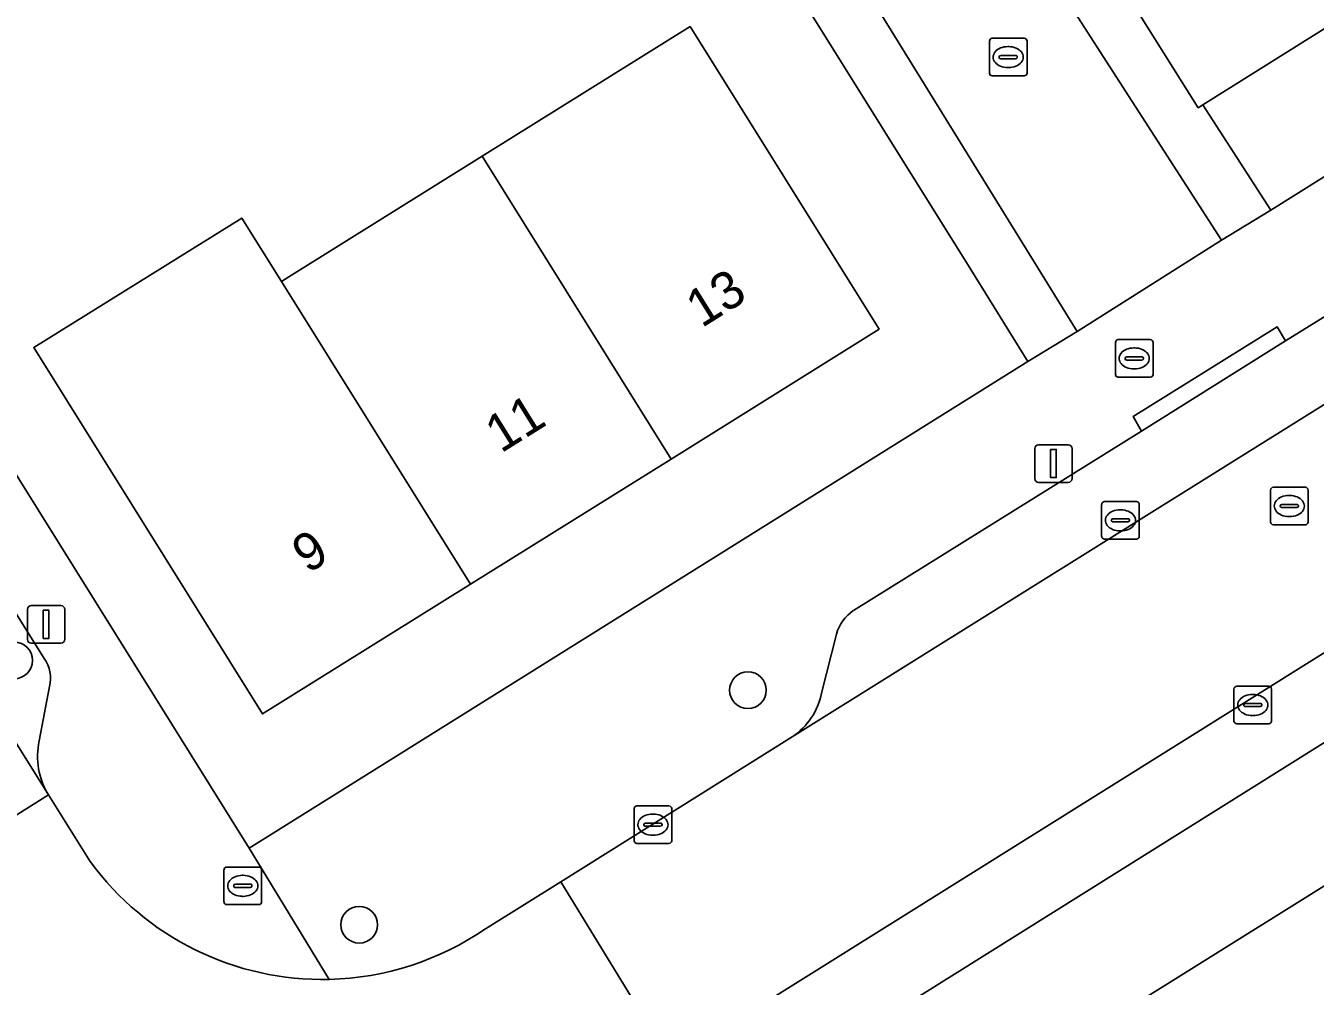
# Model space of a CAD drawing. Extents: x 159664 to 160323, y 385312 to 386115.
# Drawn here: x 160042.74 to 160077.07, y 385840.21 to 385865.77 of the extents above; entities that cross this region are included whole.
import ezdxf

# ---------------------------------------------------------------- set-up
doc = ezdxf.new("R2010")
doc.units = 0
for name, color, linetype in [('IMGEO_Boom', 7, 'Continuous'), ('IMGEO_Brandkraan', 7, 'Continuous'), ('IMGEO_Erf', 7, 'Continuous'), ('IMGEO_Kolk', 7, 'Continuous'), ('IMGEO_Lichtmast', 7, 'Continuous'), ('IMGEO_Muur', 7, 'Continuous'), ('IMGEO_Pand', 7, 'Continuous'), ('IMGEO_Pand_nummerreeks', 7, 'Continuous'), ('IMGEO_Parkeervlak_open', 7, 'Continuous'), ('IMGEO_Rijbaan_lokaal_open', 7, 'Continuous'), ('IMGEO_Rioolput', 7, 'Continuous'), ('IMGEO_Voetpad_open', 7, 'Continuous')]:
    doc.layers.add(name, color=color, linetype=linetype)

msp = doc.modelspace()

# ---------------------------------------------------------------- linework, layer by layer
at = {"layer": 'IMGEO_Boom'}
for centre in [(160042.431, 385848.879), (160061.965, 385848.085), (160051.616, 385841.843)]:
    msp.add_circle(centre, 0.489, dxfattribs=at)
at = {"layer": 'IMGEO_Brandkraan'}
for p, q in [((160071.749, 385856.491), (160071.749, 385857.343)), ((160071.824, 385857.417), (160072.676, 385857.417)), ((160072.75, 385857.343), (160072.75, 385856.491)), ((160072.008, 385856.911), (160072.008, 385856.923)), ((160072.051, 385856.96), (160072.449, 385856.96)), ((160072.237, 385857.197), (160072.262, 385857.197)), ((160072.492, 385856.923), (160072.492, 385856.911)), ((160072.446, 385856.874), (160072.048, 385856.874)), ((160072.26, 385856.637), (160072.235, 385856.637)), ((160072.676, 385856.417), (160071.824, 385856.417)), ((160048.016, 385842.452), (160048.016, 385843.304)), ((160048.091, 385843.378), (160048.943, 385843.378)), ((160049.017, 385843.304), (160049.017, 385842.452)), ((160048.275, 385842.872), (160048.275, 385842.884)), ((160048.318, 385842.921), (160048.716, 385842.921)), ((160048.504, 385843.158), (160048.529, 385843.158)), ((160048.759, 385842.884), (160048.759, 385842.872)), ((160048.713, 385842.835), (160048.315, 385842.835)), ((160048.527, 385842.598), (160048.502, 385842.598)), ((160048.943, 385842.378), (160048.091, 385842.378))]:
    msp.add_line(p, q, dxfattribs=at)
for points in [[(160071.749, 385856.491), (160071.749, 385857.343)], [(160071.824, 385857.417), (160072.676, 385857.417)], [(160072.75, 385857.343), (160072.75, 385856.491)], [(160072.676, 385856.417), (160071.824, 385856.417)], [(160048.016, 385842.452), (160048.016, 385843.304)], [(160048.091, 385843.378), (160048.943, 385843.378)], [(160049.017, 385843.304), (160049.017, 385842.452)], [(160048.943, 385842.378), (160048.091, 385842.378)]]:
    msp.add_lwpolyline(points, dxfattribs=at)
for centre, radius, start, end in [((160071.826, 385857.341), 0.0765, 91.552, 178.448), ((160071.826, 385857.341), 0.0765, 91.552, 178.448), ((160072.674, 385857.341), 0.0765, 1.552, 88.448), ((160072.674, 385857.341), 0.0765, 1.552, 88.448), ((160072.048, 385856.92), 0.0403, 85.8775, 175.7526), ((160072.453, 385856.922), 0.0386, 1.7309, 96.639), ((160072.045, 385856.91), 0.0366, 178.938, 274.7102), ((160072.449, 385856.917), 0.043, 264.8664, 352.4533), ((160071.826, 385856.493), 0.0765, 181.552, 268.448), ((160071.826, 385856.493), 0.0765, 181.552, 268.448), ((160072.674, 385856.493), 0.0765, 271.552, 358.448), ((160072.674, 385856.493), 0.0765, 271.552, 358.448), ((160048.093, 385843.302), 0.0765, 91.552, 178.448), ((160048.093, 385843.302), 0.0765, 91.552, 178.448), ((160048.941, 385843.302), 0.0765, 1.552, 88.448), ((160048.941, 385843.302), 0.0765, 1.552, 88.448), ((160048.315, 385842.881), 0.0403, 85.8775, 175.7526), ((160048.312, 385842.871), 0.0366, 178.938, 274.7102), ((160048.716, 385842.878), 0.043, 264.8664, 352.4533), ((160048.72, 385842.883), 0.0386, 1.7309, 96.639), ((160048.093, 385842.454), 0.0765, 181.552, 268.448), ((160048.093, 385842.454), 0.0765, 181.552, 268.448), ((160048.941, 385842.454), 0.0765, 271.552, 358.448), ((160048.941, 385842.454), 0.0765, 271.552, 358.448)]:
    msp.add_arc(centre, radius, start, end, dxfattribs=at)
for centre, major_axis, ratio, start_param, end_param in [((160072.236, 385856.917), (-0.387, 0.002), 0.722429, 4.712389, 7.853982), ((160072.261, 385856.917), (-0.39, 0.002), 0.717154, 1.570796, 4.712389), ((160048.503, 385842.878), (-0.387, 0.002), 0.722429, 4.712389, 7.853982), ((160048.528, 385842.878), (-0.39, 0.002), 0.717154, 1.570796, 4.712389)]:
    msp.add_ellipse(centre, major_axis=major_axis, ratio=ratio, start_param=start_param, end_param=end_param, dxfattribs=at)
at = {"layer": 'IMGEO_Erf'}
for points in [[(160017.562, 385899.151), (160016.976, 385898.786), (160016.864, 385898.967), (160013.411, 385904.508), (160011.524, 385903.327), (160035.946, 385864.298), (160048.683, 385843.877), (160069.417, 385856.837), (160067.895, 385859.287), (160061.072, 385870.217), (160056.435, 385867.318), (160052.008, 385874.381), (160051.226, 385875.622), (160036.993, 385866.722), (160033.548, 385872.248), (160030.317, 385877.411), (160029.732, 385877.045), (160029.621, 385877.223), (160026.283, 385882.566), (160026.158, 385882.766), (160027.345, 385883.508), (160024.13, 385888.65), (160020.789, 385893.991)], [(160116.716, 385886.45), (160114.912, 385889.321), (160109.699, 385886.046), (160104.61, 385882.849), (160099.521, 385879.652), (160094.432, 385876.454), (160089.342, 385873.256), (160084.253, 385870.059), (160079.165, 385866.862), (160074.076, 385863.665), (160075.884, 385860.864)], [(160042.951, 385857.21), (160048.489, 385860.652), (160049.543, 385858.965), (160049.744, 385859.091), (160054.888, 385862.299), (160060.425, 385865.751), (160065.456, 385857.696), (160059.924, 385854.239), (160054.578, 385850.905), (160049.045, 385847.455)]]:
    msp.add_lwpolyline(points, close=True, dxfattribs=at)
msp.add_lwpolyline([(160099.993, 385857.035), (160056.287, 385829.749), (160069.138, 385809.263), (160069.666, 385808.627)], dxfattribs=at)
at = {"layer": 'IMGEO_Kolk'}
for p, q in [((160068.394, 385864.512), (160068.394, 385865.364)), ((160068.469, 385865.438), (160069.321, 385865.438)), ((160068.882, 385865.218), (160068.907, 385865.218)), ((160069.395, 385865.364), (160069.395, 385864.512)), ((160068.653, 385864.932), (160068.653, 385864.944)), ((160069.091, 385864.895), (160068.693, 385864.895)), ((160068.696, 385864.981), (160069.094, 385864.981)), ((160069.137, 385864.944), (160069.137, 385864.932)), ((160068.905, 385864.658), (160068.88, 385864.658)), ((160069.321, 385864.438), (160068.469, 385864.438)), ((160071.382, 385852.181), (160071.382, 385853.033)), ((160071.457, 385853.107), (160072.309, 385853.107)), ((160071.87, 385852.887), (160071.895, 385852.887)), ((160072.383, 385853.033), (160072.383, 385852.181)), ((160071.641, 385852.601), (160071.641, 385852.613)), ((160072.079, 385852.564), (160071.681, 385852.564)), ((160071.684, 385852.65), (160072.082, 385852.65)), ((160072.125, 385852.613), (160072.125, 385852.601)), ((160071.893, 385852.327), (160071.868, 385852.327)), ((160072.309, 385852.107), (160071.457, 385852.107)), ((160074.904, 385847.265), (160074.904, 385848.117)), ((160074.979, 385848.191), (160075.831, 385848.191)), ((160075.905, 385848.117), (160075.905, 385847.265)), ((160075.163, 385847.685), (160075.163, 385847.697)), ((160075.206, 385847.734), (160075.604, 385847.734)), ((160075.392, 385847.971), (160075.417, 385847.971)), ((160075.647, 385847.697), (160075.647, 385847.685)), ((160075.601, 385847.648), (160075.203, 385847.648)), ((160075.415, 385847.411), (160075.39, 385847.411)), ((160075.831, 385847.191), (160074.979, 385847.191)), ((160058.935, 385844.08), (160058.935, 385844.932)), ((160059.01, 385845.006), (160059.862, 385845.006)), ((160059.936, 385844.932), (160059.936, 385844.08)), ((160059.423, 385844.786), (160059.448, 385844.786)), ((160059.194, 385844.5), (160059.194, 385844.512)), ((160059.632, 385844.463), (160059.234, 385844.463)), ((160059.237, 385844.549), (160059.635, 385844.549)), ((160059.446, 385844.226), (160059.421, 385844.226)), ((160059.678, 385844.512), (160059.678, 385844.5)), ((160059.862, 385844.006), (160059.01, 385844.006))]:
    msp.add_line(p, q, dxfattribs=at)
for points in [[(160068.394, 385864.512), (160068.394, 385865.364)], [(160068.469, 385865.438), (160069.321, 385865.438)], [(160069.395, 385865.364), (160069.395, 385864.512)], [(160069.321, 385864.438), (160068.469, 385864.438)], [(160071.382, 385852.181), (160071.382, 385853.033)], [(160071.457, 385853.107), (160072.309, 385853.107)], [(160072.383, 385853.033), (160072.383, 385852.181)], [(160072.309, 385852.107), (160071.457, 385852.107)], [(160074.904, 385847.265), (160074.904, 385848.117)], [(160074.979, 385848.191), (160075.831, 385848.191)], [(160075.905, 385848.117), (160075.905, 385847.265)], [(160075.831, 385847.191), (160074.979, 385847.191)], [(160058.935, 385844.08), (160058.935, 385844.932)], [(160059.01, 385845.006), (160059.862, 385845.006)], [(160059.936, 385844.932), (160059.936, 385844.08)], [(160059.862, 385844.006), (160059.01, 385844.006)]]:
    msp.add_lwpolyline(points, dxfattribs=at)
for centre, radius, start, end in [((160068.471, 385865.362), 0.0765, 91.552, 178.448), ((160068.471, 385865.362), 0.0765, 91.552, 178.448), ((160069.319, 385865.362), 0.0765, 1.552, 88.448), ((160069.319, 385865.362), 0.0765, 1.552, 88.448), ((160068.693, 385864.941), 0.0403, 85.8775, 175.7526), ((160068.69, 385864.931), 0.0366, 178.938, 274.7102), ((160069.094, 385864.938), 0.043, 264.8664, 352.4533), ((160069.098, 385864.943), 0.0386, 1.7309, 96.639), ((160068.471, 385864.514), 0.0765, 181.552, 268.448), ((160068.471, 385864.514), 0.0765, 181.552, 268.448), ((160069.319, 385864.514), 0.0765, 271.552, 358.448), ((160069.319, 385864.514), 0.0765, 271.552, 358.448), ((160071.459, 385853.031), 0.0765, 91.552, 178.448), ((160071.459, 385853.031), 0.0765, 91.552, 178.448), ((160072.307, 385853.031), 0.0765, 1.552, 88.448), ((160072.307, 385853.031), 0.0765, 1.552, 88.448), ((160071.681, 385852.61), 0.0403, 85.8775, 175.7526), ((160071.678, 385852.6), 0.0366, 178.938, 274.7102), ((160072.082, 385852.607), 0.043, 264.8664, 352.4533), ((160072.086, 385852.612), 0.0386, 1.7309, 96.639), ((160071.459, 385852.183), 0.0765, 181.552, 268.448), ((160071.459, 385852.183), 0.0765, 181.552, 268.448), ((160072.307, 385852.183), 0.0765, 271.552, 358.448), ((160072.307, 385852.183), 0.0765, 271.552, 358.448), ((160074.981, 385848.115), 0.0765, 91.552, 178.448), ((160074.981, 385848.115), 0.0765, 91.552, 178.448), ((160075.829, 385848.115), 0.0765, 1.552, 88.448), ((160075.829, 385848.115), 0.0765, 1.552, 88.448), ((160075.203, 385847.694), 0.0403, 85.8775, 175.7526), ((160075.2, 385847.684), 0.0366, 178.938, 274.7102), ((160075.604, 385847.691), 0.043, 264.8664, 352.4533), ((160075.608, 385847.696), 0.0386, 1.7309, 96.639), ((160074.981, 385847.267), 0.0765, 181.552, 268.448), ((160074.981, 385847.267), 0.0765, 181.552, 268.448), ((160075.829, 385847.267), 0.0765, 271.552, 358.448), ((160075.829, 385847.267), 0.0765, 271.552, 358.448), ((160059.012, 385844.93), 0.0765, 91.552, 178.448), ((160059.012, 385844.93), 0.0765, 91.552, 178.448), ((160059.86, 385844.93), 0.0765, 1.552, 88.448), ((160059.86, 385844.93), 0.0765, 1.552, 88.448), ((160059.234, 385844.509), 0.0403, 85.8775, 175.7526), ((160059.231, 385844.499), 0.0366, 178.938, 274.7102), ((160059.635, 385844.506), 0.043, 264.8664, 352.4533), ((160059.639, 385844.511), 0.0386, 1.7309, 96.639), ((160059.012, 385844.082), 0.0765, 181.552, 268.448), ((160059.012, 385844.082), 0.0765, 181.552, 268.448), ((160059.86, 385844.082), 0.0765, 271.552, 358.448), ((160059.86, 385844.082), 0.0765, 271.552, 358.448)]:
    msp.add_arc(centre, radius, start, end, dxfattribs=at)
for centre, major_axis, ratio, start_param, end_param in [((160068.881, 385864.938), (-0.387, 0.002), 0.722429, 4.712389, 7.853982), ((160068.906, 385864.938), (-0.39, 0.002), 0.717154, 1.570796, 4.712389), ((160071.869, 385852.607), (-0.387, 0.002), 0.722429, 4.712389, 7.853982), ((160071.894, 385852.607), (-0.39, 0.002), 0.717154, 1.570796, 4.712389), ((160075.391, 385847.691), (-0.387, 0.002), 0.722429, 4.712389, 7.853982), ((160075.416, 385847.691), (-0.39, 0.002), 0.717154, 1.570796, 4.712389), ((160059.422, 385844.506), (-0.387, 0.002), 0.722429, 4.712389, 7.853982), ((160059.447, 385844.506), (-0.39, 0.002), 0.717154, 1.570796, 4.712389)]:
    msp.add_ellipse(centre, major_axis=major_axis, ratio=ratio, start_param=start_param, end_param=end_param, dxfattribs=at)
at = {"layer": 'IMGEO_Lichtmast'}
for p, q in [((160069.604, 385853.718), (160069.604, 385854.518)), ((160069.604, 385854.518), (160069.604, 385853.718)), ((160069.704, 385854.618), (160070.494, 385854.618)), ((160070.494, 385854.618), (160069.704, 385854.618)), ((160070.594, 385854.518), (160070.594, 385853.718)), ((160070.594, 385853.718), (160070.594, 385854.518)), ((160070.494, 385853.618), (160069.704, 385853.618)), ((160069.704, 385853.618), (160070.494, 385853.618)), ((160042.786, 385849.437), (160042.786, 385850.237)), ((160042.786, 385850.237), (160042.786, 385849.437)), ((160042.886, 385850.337), (160043.676, 385850.337)), ((160043.676, 385850.337), (160042.886, 385850.337)), ((160043.776, 385850.237), (160043.776, 385849.437)), ((160043.776, 385849.437), (160043.776, 385850.237)), ((160043.676, 385849.337), (160042.886, 385849.337)), ((160042.886, 385849.337), (160043.676, 385849.337))]:
    msp.add_line(p, q, dxfattribs=at)
for points in [[(160070.024, 385854.493), (160070.174, 385854.493), (160070.174, 385853.743), (160070.024, 385853.743), (160070.024, 385854.493)], [(160043.206, 385850.212), (160043.356, 385850.212), (160043.356, 385849.462), (160043.206, 385849.462), (160043.206, 385850.212)]]:
    msp.add_lwpolyline(points, dxfattribs=at)
for centre, start, end in [((160069.704, 385854.518), 90, 180), ((160069.704, 385854.518), 90, 180), ((160070.494, 385854.518), 0, 90), ((160070.494, 385854.518), 360, 90), ((160069.704, 385853.718), 180, 270), ((160069.704, 385853.718), 180, 270), ((160070.494, 385853.718), 270, 0), ((160070.494, 385853.718), 270, 0), ((160042.886, 385850.237), 90, 180), ((160042.886, 385850.237), 90, 180), ((160043.676, 385850.237), 0, 90), ((160043.676, 385850.237), 360, 90), ((160042.886, 385849.437), 180, 270), ((160042.886, 385849.437), 180, 270), ((160043.676, 385849.437), 270, 0), ((160043.676, 385849.437), 270, 0)]:
    msp.add_arc(centre, 0.1, start, end, dxfattribs=at)
at = {"layer": 'IMGEO_Muur'}
msp.add_lwpolyline([(160061.072, 385870.217), (160067.895, 385859.287)], dxfattribs=at)
at = {"layer": 'IMGEO_Pand'}
for points in [[(160073.757, 385875.486), (160071.939, 385878.386), (160066.776, 385875.148), (160066.757, 385875.136), (160068.541, 385872.21), (160069.86, 385870.109), (160073.955, 385863.589), (160074.076, 385863.665), (160079.165, 385866.862)], [(160059.924, 385854.239), (160065.456, 385857.696), (160060.425, 385865.751), (160054.888, 385862.299)], [(160054.888, 385862.299), (160049.744, 385859.091), (160049.543, 385858.965), (160054.578, 385850.905), (160059.924, 385854.239)], [(160049.543, 385858.965), (160048.489, 385860.652), (160042.951, 385857.21), (160049.045, 385847.455), (160054.578, 385850.905)]]:
    msp.add_lwpolyline(points, close=True, dxfattribs=at)
at = {"layer": 'IMGEO_Parkeervlak_open'}
for points in [[(160043.232, 385848.929), (160010.038, 385902.057)], [(160011.905, 385895.644), (160043.342, 385845.298)], [(160063.145, 385846.843), (160091.556, 385864.586), (160112.548, 385877.672), (160134.283, 385891.268)], [(160094.471, 385859.815), (160059.908, 385838.204)], [(160079.726, 385858.134), (160079.096, 385859.135), (160076.28, 385857.388), (160072.444, 385854.983), (160064.771, 385850.208)], [(160061.36, 385838.477), (160063.193, 385838.187), (160063.548, 385838.185), (160063.951, 385838.328), (160077.936, 385847.084), (160080.915, 385848.952), (160085.398, 385851.776), (160084.692, 385852.889)], [(160064.321, 385849.579), (160063.927, 385848.006)], [(160043.097, 385846.736), (160043.374, 385848.185)]]:
    msp.add_lwpolyline(points, dxfattribs=at)
for centre, radius, start, end in [((160065.49, 385849.218), 1.224, 125.9949, 162.8436), ((160042.478, 385848.399), 0.922, 346.5464, 35.0646), ((160062.124, 385848.374), 1.84, 303.6944, 348.4719), ((160045.002, 385846.321), 1.95, 167.7029, 211.635)]:
    msp.add_arc(centre, radius, start, end, dxfattribs=at)
at = {"layer": 'IMGEO_Rijbaan_lokaal_open'}
for points in [[(160062.163, 385880.749), (160078.47, 385891.036), (160072.156, 385901.175), (160069.465, 385899.499), (160066.773, 385897.823), (160064.082, 385896.147), (160061.391, 385894.47), (160058.7, 385892.794), (160056.008, 385891.118), (160053.317, 385889.442), (160051.574, 385888.418), (160053.567, 385885.245), (160062.663, 385870.691), (160070.726, 385857.635), (160074.573, 385860.069), (160061.925, 385879.702)], [(160044.455, 385843.525), (160043.342, 385845.298), (160039.567, 385842.92), (160040.814, 385840.914)], [(160056.584, 385836.115), (160059.908, 385838.204), (160056.983, 385842.985), (160054.98, 385841.736)]]:
    msp.add_lwpolyline(points, dxfattribs=at)
for points in [[(160039.567, 385842.92), (160043.342, 385845.298), (160011.905, 385895.644), (160008.124, 385893.283), (160039.334, 385843.293)], [(160094.471, 385859.815), (160091.556, 385864.586), (160063.145, 385846.843), (160056.983, 385842.985), (160059.908, 385838.204)]]:
    msp.add_lwpolyline(points, close=True, dxfattribs=at)
for centre, radius, start, end in [((160050.638, 385848.045), 7.659, 216.1655, 271.3544), ((160050.635, 385848.051), 7.665, 271.3725, 304.528)]:
    msp.add_arc(centre, radius, start, end, dxfattribs=at)
at = {"layer": 'IMGEO_Rioolput'}
for p, q in [((160075.953, 385853.488), (160076.805, 385853.488)), ((160075.878, 385852.562), (160075.878, 385853.414)), ((160076.366, 385853.268), (160076.391, 385853.268)), ((160076.879, 385853.414), (160076.879, 385852.562)), ((160076.137, 385852.982), (160076.137, 385852.994)), ((160076.575, 385852.945), (160076.177, 385852.945)), ((160076.18, 385853.031), (160076.578, 385853.031)), ((160076.621, 385852.994), (160076.621, 385852.982)), ((160076.805, 385852.488), (160075.953, 385852.488)), ((160076.389, 385852.708), (160076.364, 385852.708))]:
    msp.add_line(p, q, dxfattribs=at)
for points in [[(160075.953, 385853.488), (160076.805, 385853.488)], [(160075.878, 385852.562), (160075.878, 385853.414)], [(160076.879, 385853.414), (160076.879, 385852.562)], [(160076.805, 385852.488), (160075.953, 385852.488)]]:
    msp.add_lwpolyline(points, dxfattribs=at)
for centre, radius, start, end in [((160075.955, 385853.412), 0.0765, 91.552, 178.448), ((160075.955, 385853.412), 0.0765, 91.552, 178.448), ((160076.803, 385853.412), 0.0765, 1.552, 88.448), ((160076.803, 385853.412), 0.0765, 1.552, 88.448), ((160076.177, 385852.991), 0.0403, 85.8775, 175.7526), ((160076.174, 385852.981), 0.0366, 178.938, 274.7102), ((160076.578, 385852.988), 0.043, 264.8664, 352.4533), ((160076.582, 385852.993), 0.0386, 1.7309, 96.639), ((160075.955, 385852.564), 0.0765, 181.552, 268.448), ((160075.955, 385852.564), 0.0765, 181.552, 268.448), ((160076.803, 385852.564), 0.0765, 271.552, 358.448), ((160076.803, 385852.564), 0.0765, 271.552, 358.448)]:
    msp.add_arc(centre, radius, start, end, dxfattribs=at)
for centre, major_axis, ratio, start_param, end_param in [((160076.365, 385852.988), (-0.387, 0.002), 0.722429, 4.712389, 7.853982), ((160076.39, 385852.988), (-0.39, 0.002), 0.717154, 1.570796, 4.712389)]:
    msp.add_ellipse(centre, major_axis=major_axis, ratio=ratio, start_param=start_param, end_param=end_param, dxfattribs=at)
at = {"layer": 'IMGEO_Voetpad_open'}
for points in [[(159928.962, 386031.821), (160007.649, 385905.881), (160007.996, 385906.094), (160010.404, 385902.292), (160010.038, 385902.057), (160043.232, 385848.929)], [(160141.001, 385901.665), (160139.28, 385900.589), (160118.445, 385887.533), (160116.716, 385886.45), (160075.884, 385860.864), (160074.573, 385860.069), (160070.726, 385857.635), (160069.417, 385856.837), (160048.683, 385843.877), (160050.819, 385840.388)], [(160064.771, 385850.208), (160072.444, 385854.983), (160072.221, 385855.373), (160076.054, 385857.762), (160076.28, 385857.388), (160079.096, 385859.135), (160078.564, 385859.903), (160081.927, 385861.962), (160082.406, 385861.229), (160091.151, 385866.716), (160090.725, 385867.449), (160092.858, 385868.751), (160093.257, 385868.13), (160099.827, 385872.1), (160101.83, 385873.354), (160121.825, 385885.847)], [(160061.925, 385879.702), (160074.573, 385860.069), (160075.884, 385860.864), (160074.076, 385863.665), (160073.955, 385863.589), (160069.86, 385870.109)], [(160062.04, 385870.818), (160061.072, 385870.217), (160067.895, 385859.287), (160069.417, 385856.837), (160070.726, 385857.635), (160062.663, 385870.691)], [(160050.819, 385840.388), (160048.683, 385843.877), (160035.946, 385864.298)], [(160054.069, 385833.285), (160056.287, 385829.749), (160099.993, 385857.035)], [(160092.943, 385856.498), (160088.43, 385853.673), (160089.062, 385852.649), (160086.03, 385850.763), (160085.398, 385851.776), (160080.915, 385848.952), (160081.143, 385848.591), (160078.168, 385846.722), (160077.936, 385847.084), (160063.951, 385838.328), (160063.548, 385838.185), (160063.193, 385838.187), (160061.36, 385838.477)], [(160063.927, 385848.006), (160064.321, 385849.579)], [(160043.374, 385848.185), (160043.097, 385846.736)], [(160054.98, 385841.736), (160056.983, 385842.985), (160063.145, 385846.843)], [(160043.342, 385845.298), (160044.455, 385843.525)]]:
    msp.add_lwpolyline(points, dxfattribs=at)
msp.add_lwpolyline([(160072.444, 385854.983), (160076.28, 385857.388), (160076.054, 385857.762), (160072.221, 385855.373)], close=True, dxfattribs=at)
for centre, radius, start, end in [((160065.49, 385849.218), 1.224, 125.9949, 162.8436), ((160042.478, 385848.399), 0.922, 346.5464, 35.0646), ((160062.124, 385848.374), 1.84, 303.6944, 348.4719), ((160045.002, 385846.321), 1.95, 167.7029, 211.635), ((160050.638, 385848.045), 7.659, 216.1655, 271.3544), ((160050.635, 385848.051), 7.665, 271.3725, 304.528)]:
    msp.add_arc(centre, radius, start, end, dxfattribs=at)

# ---------------------------------------------------------------- texts
at = {"layer": 'IMGEO_Pand_nummerreeks'}
for s, rotation, p in [('13', 32.0046, (160060.733, 385857.716)), ('11', 31.9481, (160055.389, 385854.381)), ('9', 31.9481, (160050.245, 385851.173))]:
    msp.add_text(s, height=1, rotation=rotation, dxfattribs=at).set_placement(p)

doc.saveas('drawing.dxf')
